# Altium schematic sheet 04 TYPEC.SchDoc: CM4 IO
size 420 x 297 mm; Page Create Date: March  8, 1995; Page Number: 4; Page Size: A3; Comment: radxa_1010; Page Count: 19; RevCode: V1.10; Doc: 04 TYPEC; DsnPath: D:\WMS\黄工\[RC126]CM4_IO_V1.10\[RC126]_V1.10\CM4 IO_V1.10.DSN; SchematicName: CM4 IO V1.10; PageName: 04 TYPEC; PageSize: A3; TopSchematic: True
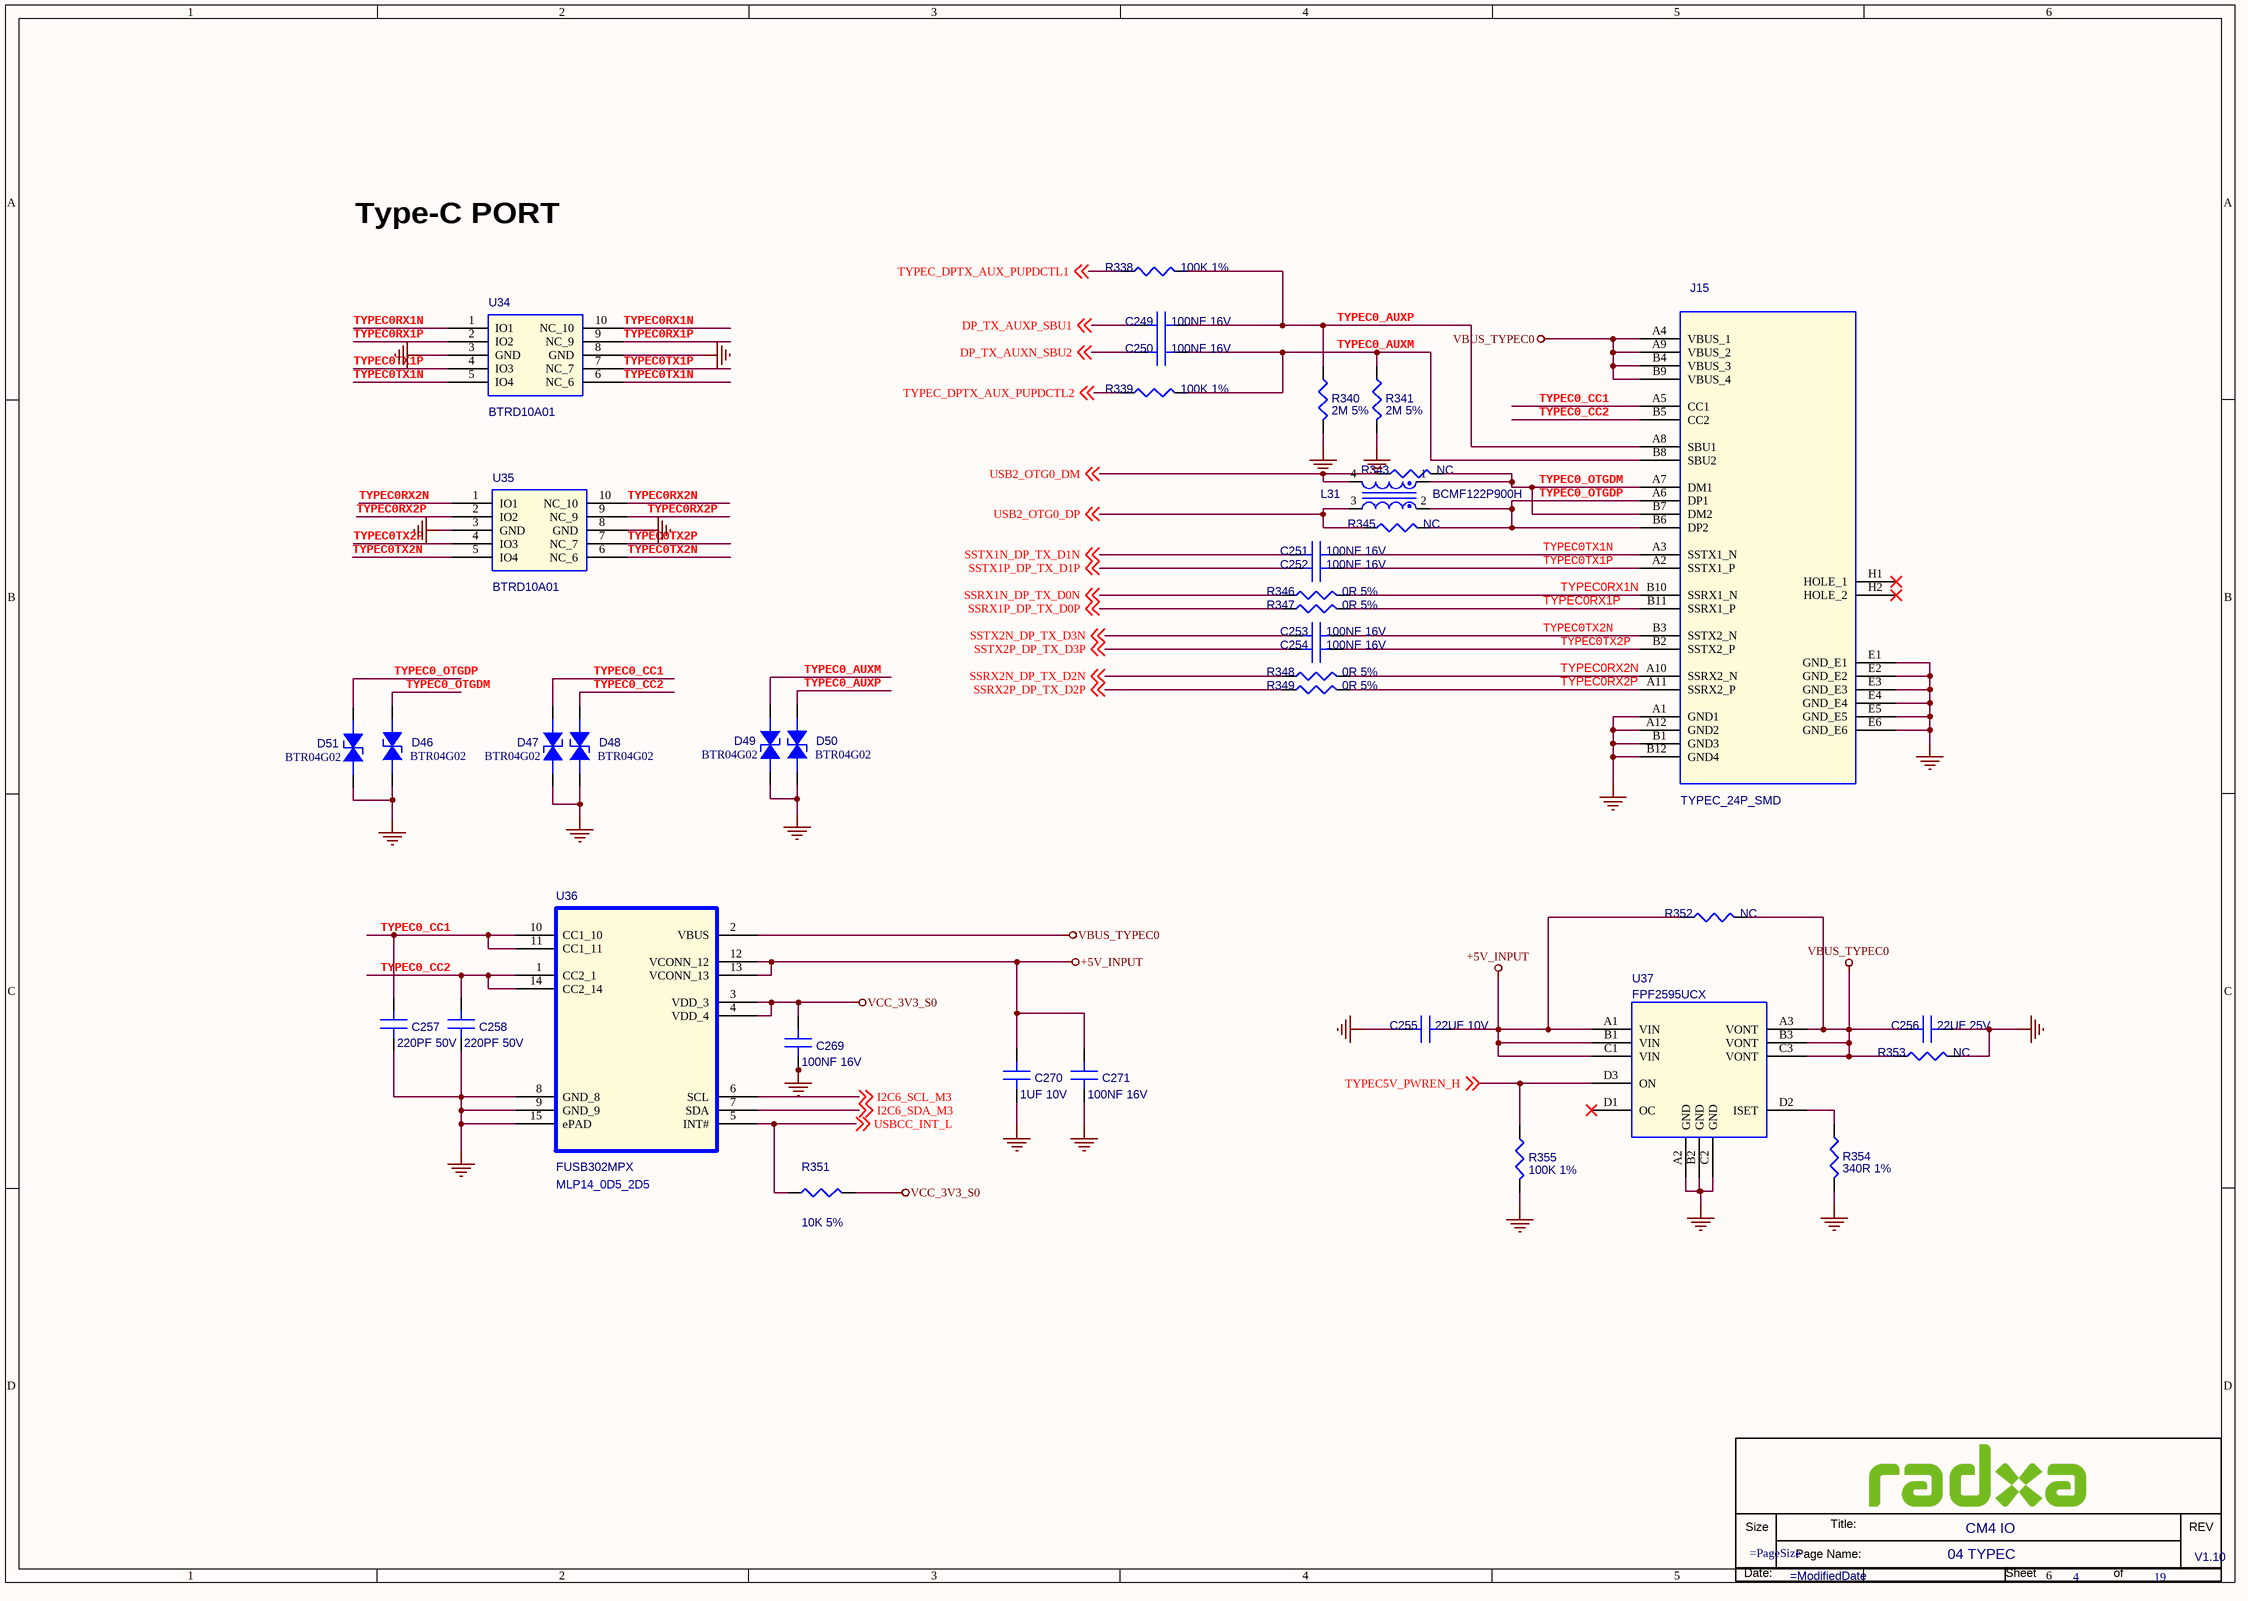
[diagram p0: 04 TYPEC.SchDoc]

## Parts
*  Doc: 04 TYPEC  RevCode: V1.10  Title: CM4 IO  Page Number: 4  Page Count: 19  (hidden comment: radxa_1010)  (graphical)
C249  100NF 16V  [C0201]
C250  100NF 16V  [C0201]
C251  100NF 16V  [C0201]
C252  100NF 16V  [C0201]
C253  100NF 16V  [C0201]
C254  100NF 16V  [C0201]
C255  22UF 10V  [C0603]
C256  22UF 25V  [C0805]
C257  220PF 50V  [C0201]
C258  220PF 50V  [C0201]
C269  100NF 16V  [C0201]
C270  1UF 10V  [C0201]
C271  100NF 16V  [C0201]
D46  BTR04G02  [DFN1006-2L]
D47  BTR04G02  [DFN1006-2L]
D48  BTR04G02  [DFN1006-2L]
D49  BTR04G02  [DFN1006-2L]
D50  BTR04G02  [DFN1006-2L]
D51  BTR04G02  [DFN1006-2L]
J15  TYPEC_24P_SMD  [TYPEC_SM24P_0D5]
L31  BCMF122P900H  [LC1210]
R338  100K 1%  [R0402]
R339  100K 1%  [R0402]
R340  2M 5%  [R0402]
R341  2M 5%  [R0402]
R343  NC  [R0402]
R345  NC  [R0402]
R346  0R 5%  [R0402]
R347  0R 5%  [R0402]
R348  0R 5%  [R0402]
R349  0R 5%  [R0402]
R351  10K 5%  [R0402]
R352  NC  [R0402]
R353  NC  [R0402]
R354  340R 1%  [R0402]
R355  100K 1%  [R0402]
U34  BTRD10A01  [SON10_0D5_1]
U35  BTRD10A01  [SON10_0D5_1]
U36  FUSB302MPX  [MLP14_0D5_2D5]
U37  FPF2595UCX  [WLCSP12_0D4_1D5]

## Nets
+5V_INPUT: C255.1(A) C270.1(A) C271.1(A) R352.1 U36.12(VCONN_12) U36.13(VCONN_13) U37.A1(VIN) U37.B1(VIN) U37.C1(VIN)
GND: C255.2(B) C256.2(B) C257.2(B) C258.2(B) C269.2(B) C270.2(B) C271.2(B) D46.1(ANODE) D47.1(ANODE) D48.1(ANODE) D49.1(ANODE) D50.1(ANODE) D51.1(ANODE) J15.A1(GND1) J15.A12(GND2) J15.B1(GND3) J15.B12(GND4) J15.E1(GND_E1) J15.E2(GND_E2) J15.E3(GND_E3) J15.E4(GND_E4) J15.E5(GND_E5) J15.E6(GND_E6) R340.2 R341.2 R353.2 R354.2 R355.2 U34.3(GND) U34.8(GND) U35.3(GND) U35.8(GND) U36.8(GND_8) U36.9(GND_9) U36.15(ePAD) U37.A2(GND) U37.B2(GND) U37.C2(GND)
VBUS_TYPEC0: C256.1(A) J15.A4(VBUS_1) J15.A9(VBUS_2) J15.B4(VBUS_3) J15.B9(VBUS_4) R352.2 R353.1 U36.2(VBUS) U37.A3(VONT) U37.B3(VONT) U37.C3(VONT)
VCC_3V3_S0: C269.1(A) R351.1 U36.3(VDD_3) U36.4(VDD_4)
DP_TX_AUXN_SBU2: C250.1(A) ; off-sheet DP_TX_AUXN_SBU2
DP_TX_AUXP_SBU1: C249.1(A) ; off-sheet DP_TX_AUXP_SBU1
I2C6_SCL_M3: U36.6(SCL) ; off-sheet I2C6_SCL_M3
I2C6_SDA_M3: U36.7(SDA) ; off-sheet I2C6_SDA_M3
SSRX1N_DP_TX_D0N: R346.1 ; off-sheet SSRX1N_DP_TX_D0N
SSRX1P_DP_TX_D0P: R347.1 ; off-sheet SSRX1P_DP_TX_D0P
SSRX2N_DP_TX_D2N: R348.1 ; off-sheet SSRX2N_DP_TX_D2N
SSRX2P_DP_TX_D2P: R349.1 ; off-sheet SSRX2P_DP_TX_D2P
SSTX1N_DP_TX_D1N: C251.1(A) ; off-sheet SSTX1N_DP_TX_D1N
SSTX1P_DP_TX_D1P: C252.1(A) ; off-sheet SSTX1P_DP_TX_D1P
SSTX2N_DP_TX_D3N: C253.1(A) ; off-sheet SSTX2N_DP_TX_D3N
SSTX2P_DP_TX_D3P: C254.1(A) ; off-sheet SSTX2P_DP_TX_D3P
TYPEC0_AUXM: C250.2(B) D49.2(CATHODE) J15.B8(SBU2) R339.2 R341.1
TYPEC0_AUXP: C249.2(B) D50.2(CATHODE) J15.A8(SBU1) R338.2 R340.1
TYPEC0_CC1: C257.1(A) D47.2(CATHODE) J15.A5(CC1) U36.10(CC1_10) U36.11(CC1_11)
TYPEC0_CC2: C258.1(A) D48.2(CATHODE) J15.B5(CC2) U36.1(CC2_1) U36.14(CC2_14)
TYPEC0_OTGDM: D46.2(CATHODE) J15.A7(DM1) J15.B7(DM2) L31.1 R343.2
TYPEC0_OTGDP: D51.2(CATHODE) J15.A6(DP1) J15.B6(DP2) L31.2 R345.2
TYPEC0RX1N: J15.B10(SSRX1_N) R346.2 U34.1(IO1) U34.10(NC_10)
TYPEC0RX1P: J15.B11(SSRX1_P) R347.2 U34.2(IO2) U34.9(NC_9)
TYPEC0RX2N: J15.A10(SSRX2_N) R348.2 U35.1(IO1) U35.10(NC_10)
TYPEC0RX2P: J15.A11(SSRX2_P) R349.2 U35.2(IO2) U35.9(NC_9)
TYPEC0TX1N: C251.2(B) J15.A3(SSTX1_N) U34.5(IO4) U34.6(NC_6)
TYPEC0TX1P: C252.2(B) J15.A2(SSTX1_P) U34.4(IO3) U34.7(NC_7)
TYPEC0TX2N: C253.2(B) J15.B3(SSTX2_N) U35.5(IO4) U35.6(NC_6)
TYPEC0TX2P: C254.2(B) J15.B2(SSTX2_P) U35.4(IO3) U35.7(NC_7)
TYPEC5V_PWREN_H: R355.1 U37.D3(ON) ; off-sheet TYPEC5V_PWREN_H
TYPEC_DPTX_AUX_PUPDCTL1: R338.1 ; off-sheet TYPEC_DPTX_AUX_PUPDCTL1
TYPEC_DPTX_AUX_PUPDCTL2: R339.1 ; off-sheet TYPEC_DPTX_AUX_PUPDCTL2
USB2_OTG0_DM: L31.4 R343.1 ; off-sheet USB2_OTG0_DM
USB2_OTG0_DP: L31.3 R345.1 ; off-sheet USB2_OTG0_DP
USBCC_INT_L: R351.2 U36.5(INT#) ; off-sheet USBCC_INT_L
NetR354_1: R354.1 U37.D2(ISET)

Not connected (* = marked no-connect by the designer): J15 H1(HOLE_1)* H2(HOLE_2)*; U37 D1(OC)*

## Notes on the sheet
- Type-C PORT

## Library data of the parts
C249 = C: SMD  0201  100NF  16V  X5R  ±20%  ROHS; PARTS: 1; Part Reference: C249; Part Number: A1C01.00099; OriginalSymbolOrigin: (0,30); PKG_TYPE: CAP2-100-250; LEVEL: STD; PINSWAP: (A,B); Preferred: 6715f349cd0bc5
C250 = C: SMD  0201  100NF  16V  X5R  ±20%  ROHS; PARTS: 1; Part Reference: C250; Part Number: A1C01.00099; OriginalSymbolOrigin: (0,30); PKG_TYPE: CAP2-100-250; LEVEL: STD; PINSWAP: (A,B); Preferred: 6715f349cd0bc5
C251 = C: SMD  0201  100NF  16V  X5R  ±20%  ROHS; PARTS: 1; Part Reference: C251; Part Number: A1C01.00099; OriginalSymbolOrigin: (0,30); PKG_TYPE: CAP2-100-250; LEVEL: STD; PINSWAP: (A,B); Preferred: 6715f349cd0bc5
C252 = C: SMD  0201  100NF  16V  X5R  ±20%  ROHS; PARTS: 1; Part Reference: C252; Part Number: A1C01.00099; OriginalSymbolOrigin: (0,30); PKG_TYPE: CAP2-100-250; LEVEL: STD; PINSWAP: (A,B); Preferred: 6715f349cd0bc5
C253 = C: SMD  0201  100NF  16V  X5R  ±20%  ROHS; PARTS: 1; Part Reference: C253; Part Number: A1C01.00099; OriginalSymbolOrigin: (0,30); PKG_TYPE: CAP2-100-250; LEVEL: STD; PINSWAP: (A,B); Preferred: 6715f349cd0bc5
C254 = C: SMD  0201  100NF  16V  X5R  ±20%  ROHS; PARTS: 1; Part Reference: C254; Part Number: A1C01.00099; OriginalSymbolOrigin: (0,30); PKG_TYPE: CAP2-100-250; LEVEL: STD; PINSWAP: (A,B); Preferred: 6715f349cd0bc5
C255 = C: SMD  0603  22UF  10V  X5R  ±20%  ROHS; PARTS: 1; Part Reference: C255; Part Number: A1C01.00015; OriginalSymbolOrigin: (0,30); PKG_TYPE: CAP2-100-250; LEVEL: STD; PINSWAP: (A,B); Preferred: 6715f349cd0bc5
C256 = C: SMD  0805  22UF  25V  X5R  ±20%  ROHS; PARTS: 1; Part Reference: C256; Part Number: A1C01.00249; OriginalSymbolOrigin: (0,30); PKG_TYPE: CAP2-100-250; LEVEL: STD; PINSWAP: (A,B); Preferred: 6715f349cd0bc5
C257 = C: SMD  0201  220PF  50V  NPO  ±5%  ROHS; PARTS: 1; Part Reference: C257; Part Number: A1C01.00383; OriginalSymbolOrigin: (0,30); PKG_TYPE: CAP2-100-250; LEVEL: STD; PINSWAP: (A,B); Preferred: 6715f349cd0bc5
C258 = C: SMD  0201  220PF  50V  NPO  ±5%  ROHS; PARTS: 1; Part Reference: C258; Part Number: A1C01.00383; OriginalSymbolOrigin: (0,30); PKG_TYPE: CAP2-100-250; LEVEL: STD; PINSWAP: (A,B); Preferred: 6715f349cd0bc5
C269 = C: SMD  0201  100NF  16V  X5R  ±20%  ROHS; PARTS: 1; Part Reference: C269; Part Number: A1C01.00099; OriginalSymbolOrigin: (0,30); PKG_TYPE: CAP2-100-250; LEVEL: STD; PINSWAP: (A,B); Preferred: 6715f349cd0bc5
C270 = C: SMD  0201  1UF  10V  X5R  ±20%  ROHS; PARTS: 1; Part Reference: C270; Part Number: A1C01.00081; OriginalSymbolOrigin: (0,30); PKG_TYPE: CAP2-100-250; LEVEL: STD; PINSWAP: (A,B); Preferred: 6715f349cd0bc5
C271 = C: SMD  0201  100NF  16V  X5R  ±20%  ROHS; PARTS: 1; Part Reference: C271; Part Number: A1C01.00099; OriginalSymbolOrigin: (0,30); PKG_TYPE: CAP2-100-250; LEVEL: STD; PINSWAP: (A,B); Preferred: 6715f349cd0bc5
D46 = ESD: SMD  编带  0402  BTR04G02  B-tron  ROHS; Part Reference: D46; Part Number: A1D02.00002; Parameter: ESD-台舟 ESD5341N-封装 esd0402; ID: DE-E0004; Preferred: 6715f349cd0bc5; Temp Coeff: -50℃ to +125℃; PCB Footprint: ESD_D0402
D47 = ESD: SMD  编带  0402  BTR04G02  B-tron  ROHS; Part Reference: D47; Part Number: A1D02.00002; Parameter: ESD-台舟 ESD5341N-封装 esd0402; ID: DE-E0004; Preferred: 6715f349cd0bc5; Temp Coeff: -50℃ to +125℃; PCB Footprint: ESD_D0402
D48 = ESD: SMD  编带  0402  BTR04G02  B-tron  ROHS; Part Reference: D48; Part Number: A1D02.00002; Parameter: ESD-台舟 ESD5341N-封装 esd0402; ID: DE-E0004; Preferred: 6715f349cd0bc5; Temp Coeff: -50℃ to +125℃; PCB Footprint: ESD_D0402
D49 = ESD: SMD  编带  0402  BTR04G02  B-tron  ROHS; Part Reference: D49; Part Number: A1D02.00002; Parameter: ESD-台舟 ESD5341N-封装 esd0402; ID: DE-E0004; Temp Coeff: -50℃ to +125℃; Preferred: 6715f349cd0bc5; PCB Footprint: ESD_D0402
D50 = ESD: SMD  编带  0402  BTR04G02  B-tron  ROHS; Part Reference: D50; Part Number: A1D02.00002; Parameter: ESD-台舟 ESD5341N-封装 esd0402; ID: DE-E0004; Temp Coeff: -50℃ to +125℃; Preferred: 6715f349cd0bc5; PCB Footprint: ESD_D0402
D51 = ESD: SMD  编带  0402  BTR04G02  B-tron  ROHS; Part Reference: D51; Part Number: A1D02.00002; Parameter: ESD-台舟 ESD5341N-封装 esd0402; ID: DE-E0004; Preferred: 6715f349cd0bc5; Temp Coeff: -50℃ to +125℃; PCB Footprint: ESD_D0402
J15 = TYPEC_24P_SMD_2: SMD  母座  2*12PIN  双排  8.94x7.9xH3.2mm  带定位柱  不锈钢  兴联  BUSF242B3N11677  ROHS; Part Reference: J15; Part Number: A1J04.00021; Preferred: 6715f349cd0bc5; Temp Coeff: -25℃ to +85℃
L31 = MCZ1210AH900L2: SMD  BCMF122P900H  90R  4PIN  不带ESD  ±5%  B-tron  ROHS; Part Reference: L31; Part Number: A1L03.00003; PCB Footprint: CML_SM4_0D6_1D5; Preferred: 6715f349cd0bc5; Temp Coeff: -40℃ to +105℃
R338 = R: SMD  0201  100K  1/20W  ±1%  ROHS; Part Reference: R338; Part Number: A1R01.00165; Preferred: 6715f349cd0bc5
R339 = R: SMD  0201  100K  1/20W  ±1%  ROHS; Part Reference: R339; Part Number: A1R01.00165; PCB Footprint: R0201; Preferred: 6715f349cd0bc5
R340 = R: SMD  0201  2M  1/20W  ±5%  ROHS; Part Reference: R340; Part Number: A1R01.00114; PCB Footprint: R0201; Temp Coeff: -55℃ to +125℃; Preferred: 6715f349cd0bc5
R341 = R: SMD  0201  2M  1/20W  ±5%  ROHS; Part Reference: R341; Part Number: A1R01.00114; PCB Footprint: R0201; Temp Coeff: -55℃ to +125℃; Preferred: 6715f349cd0bc5
R343 = R: SMD  0201  0R  1/20W  ±5%  ROHS; Part Reference: R343; Part Number: A1R01.00027; PCB Footprint: R0201; Temp Coeff: -55℃ to +125℃; Preferred: 6715f349cd0bc5
R345 = R: SMD  0201  0R  1/20W  ±5%  ROHS; Part Reference: R345; Part Number: A1R01.00027; PCB Footprint: R0201; Preferred: 6715f349cd0bc5; Temp Coeff: -55℃ to +125℃
R346 = R: SMD  0201  0R  1/20W  ±5%  ROHS; Part Reference: R346; Part Number: A1R01.00027; PCB Footprint: R0201; Temp Coeff: -55℃ to +125℃; Preferred: 6715f349cd0bc5
R347 = R: SMD  0201  0R  1/20W  ±5%  ROHS; Part Reference: R347; Part Number: A1R01.00027; PCB Footprint: R0201; Temp Coeff: -55℃ to +125℃; Preferred: 6715f349cd0bc5
R348 = R: SMD  0201  0R  1/20W  ±5%  ROHS; Part Reference: R348; Part Number: A1R01.00027; PCB Footprint: R0201; Temp Coeff: -55℃ to +125℃; Preferred: 6715f349cd0bc5
R349 = R: SMD  0201  0R  1/20W  ±5%  ROHS; Part Reference: R349; Part Number: A1R01.00027; PCB Footprint: R0201; Temp Coeff: -55℃ to +125℃; Preferred: 6715f349cd0bc5
R351 = R: SMD  0201  10K  1/20W  ±5%  ROHS; Part Reference: R351; Part Number: A1R01.00012; Temp Coeff: -55℃ to +125℃; Preferred: 6715f349cd0bc5
R352 = R: SMD  0402  0R  1/16W  ±5%  ROHS; Part Reference: R352; Part Number: A1R01.00030; Temp Coeff: -55℃ to +155℃; Preferred: 6715f349cd0bc5
R353 = R: SMD  0201  4.7K  1/20W  ±5%  ROHS; Part Reference: R353; Part Number: A1R01.00014; PCB Footprint: R0201; Preferred: 6715f349cd0bc5; Temp Coeff: -55℃ to +125℃
R354 = R: SMD  0201  340R  1/20W  ±1%  ROHS; Part Reference: R354; Part Number: A1R01.00512; PCB Footprint: R0201; Temp Coeff: -55℃ to +125℃; Preferred: 6715f349cd0bc5
R355 = R: SMD  0201  100K  1/20W  ±1%  ROHS; Part Reference: R355; Part Number: A1R01.00165; PCB Footprint: R0201; Preferred: 6715f349cd0bc5
U34 = BTRD10A01: SMD  编带  DFN2510-10L  BTRD10A01  4Line  0.1pF  B-tron  ROHS; Part Reference: U34; Part Number: A1D02.00106; Preferred: 6715f349cd0bc5; Temp Coeff: -55℃ to +125℃
U35 = BTRD10A01: SMD  编带  DFN2510-10L  BTRD10A01  4Line  0.1pF  B-tron  ROHS; Part Reference: U35; Part Number: A1D02.00106; Preferred: 6715f349cd0bc5; Temp Coeff: -55℃ to +125℃
U36 = FUSB302MPX: SMD  USB转换芯片  FUSB302MPX  MLP14  onsemi(安森美)  ROHS; Part Reference: U36; Part Number: A1I01.00760; Temp Coeff: -40℃ to +85℃; Preferred: 6715f349cd0bc5
U37 = FPF2595UCX: SMD  功率电子开关  FPF2595UCX  WLCSP12  ON(安森美)  ROHS; Part Reference: U37; Part Number: A1I01.00675; Preferred: 6715f349cd0bc5; Temp Coeff: -40℃ to +85℃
